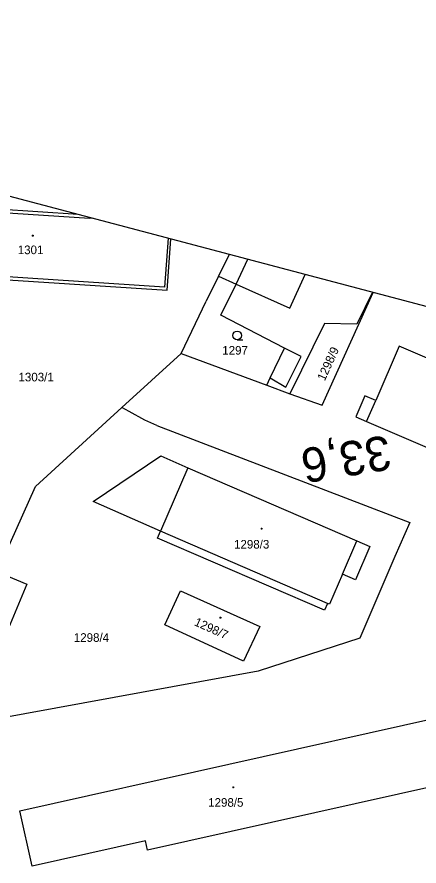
# Model space of a CAD drawing. Extents: x -805011 to -803920, y -1150790 to -1150234.
# Drawn here: x -804499.4 to -804429.5, y -1150466 to -1150318.2 of the extents above; entities that cross this region are included whole.
import ezdxf

# ---------------------------------------------------------------- set-up
doc = ezdxf.new("R2010")
doc.units = 0
for name, color, linetype in [('Default', 7, 'Continuous'), ('formát', 7, 'Continuous'), ('kilometráž - vrstava 7', 7, 'Continuous'), ('kn_celek - Cisla pozemkovych parcel', 7, 'Continuous'), ('kn_celek - Cisla stavebnich parcel', 7, 'Continuous'), ('kn_celek - Hranice parcel', 7, 'Continuous'), ('kn_celek - Vnitrni kresby', 7, 'Continuous'), ('kn_celek - Znacky budov', 7, 'Continuous'), ('kn_celek - Znacky kultur', 7, 'Continuous')]:
    doc.layers.add(name, color=color, linetype=linetype)

# ---------------------------------------------------------------- blocks, each defined once
blk = doc.blocks.new('304')
at = {"layer": 'Default'}
blk.add_line((-0.1, 0), (9.9, 0), dxfattribs=at)
blk.add_circle((-0.1, 7.5), 7.5, dxfattribs=at)
blk = doc.blocks.new('402')
at = {"layer": 'Default'}
for p, q in [((-0.8, 0.8), (0.7, 0.8)), ((-0.8, 0.8), (-0.8, -0.7)), ((0.7, 0.8), (0.7, -0.7)), ((0.7, -0.7), (-0.8, -0.7))]:
    blk.add_line(p, q, dxfattribs=at)

msp = doc.modelspace()

# ---------------------------------------------------------------- linework, layer by layer
at = {"layer": 'formát'}
msp.add_line((-804326.3, -1150395.58), (-804935.34, -1150234.42), dxfattribs=at)
at = {"layer": 'kn_celek - Hranice parcel'}
for p, q in [((-804488.71, -1150352.61), (-804503.36, -1150351.63)), ((-804473.23, -1150365.78), (-804472.61, -1150356.87)), ((-804464.31, -1150363.35), (-804462.43, -1150359.56)), ((-804519.49, -1150362.73), (-804473.23, -1150365.78)), ((-804464.31, -1150363.35), (-804466.46, -1150367.67)), ((-804464.31, -1150363.35), (-804461.25, -1150364.73)), ((-804463.92, -1150370.13), (-804461.25, -1150364.73)), ((-804446.28, -1150385.78), (-804437.43, -1150366.18)), ((-804437.55, -1150366.14), (-804440.24, -1150371.68)), ((-804470.79, -1150376.79), (-804466.46, -1150367.67)), ((-804452.82, -1150375.84), (-804463.92, -1150370.13)), ((-804445.89, -1150371.55), (-804451.93, -1150383.79)), ((-804440.24, -1150371.68), (-804445.89, -1150371.55)), ((-804455.33, -1150381.05), (-804452.82, -1150375.84)), ((-804432.88, -1150375.5), (-804436.98, -1150384.97)), ((-804404.52, -1150387.76), (-804432.88, -1150375.5)), ((-804470.79, -1150376.79), (-804481.13, -1150386.22)), ((-804470.79, -1150376.79), (-804455.94, -1150382.3)), ((-804455.94, -1150382.3), (-804455.33, -1150381.05)), ((-804455.94, -1150382.3), (-804451.93, -1150383.79)), ((-804451.93, -1150383.79), (-804446.28, -1150385.78)), ((-804438.88, -1150384.15), (-804440.46, -1150387.81)), ((-804436.98, -1150384.97), (-804438.88, -1150384.15)), ((-804496.15, -1150399.93), (-804481.13, -1150386.22)), ((-804479.87, -1150386.91), (-804481.13, -1150386.22)), ((-804477.15, -1150388.39), (-804479.87, -1150386.91)), ((-804475.07, -1150389.32), (-804477.15, -1150388.39)), ((-804440.46, -1150387.81), (-804438.58, -1150388.63)), ((-804438.58, -1150388.63), (-804410.14, -1150400.87)), ((-804475.07, -1150389.32), (-804431.06, -1150406.23)), ((-804486.1, -1150402.56), (-804474.37, -1150394.64)), ((-804474.37, -1150394.64), (-804469.64, -1150396.73)), ((-804469.64, -1150396.73), (-804440.25, -1150409.44)), ((-804507.58, -1150425.47), (-804496.15, -1150399.93)), ((-804474.41, -1150407.75), (-804486.1, -1150402.56)), ((-804431.06, -1150406.23), (-804433.64, -1150412.12)), ((-804474.93, -1150408.95), (-804474.41, -1150407.75)), ((-804445.88, -1150421.51), (-804474.93, -1150408.95)), ((-804440.25, -1150409.44), (-804438.01, -1150410.41)), ((-804438.01, -1150410.41), (-804440.51, -1150416.19)), ((-804433.64, -1150412.12), (-804439.74, -1150426.35)), ((-804501.23, -1150415.44), (-804497.65, -1150416.93)), ((-804442.75, -1150415.22), (-804445.02, -1150420.46)), ((-804440.51, -1150416.19), (-804442.75, -1150415.22)), ((-804497.65, -1150416.93), (-804501.68, -1150426.69)), ((-804473.68, -1150424.06), (-804470.93, -1150418.09)), ((-804470.93, -1150418.09), (-804457.13, -1150424.3)), ((-804445.36, -1150420.31), (-804445.88, -1150421.51)), ((-804445.02, -1150420.46), (-804445.36, -1150420.31)), ((-804459.96, -1150430.39), (-804473.68, -1150424.06)), ((-804457.13, -1150424.3), (-804459.96, -1150430.39)), ((-804439.74, -1150426.35), (-804457.42, -1150432.08)), ((-804457.42, -1150432.08), (-804541.27, -1150447.49)), ((-804498.86, -1150456.4), (-804426.19, -1150440.19)), ((-804425.85, -1150451.92), (-804476.67, -1150463.25)), ((-804496.72, -1150466.03), (-804498.86, -1150456.4)), ((-804477.02, -1150461.66), (-804496.72, -1150466.03)), ((-804476.67, -1150463.25), (-804477.02, -1150461.66))]:
    msp.add_line(p, q, dxfattribs=at)
at = {"layer": 'kn_celek - Vnitrni kresby'}
for p, q in [((-804503.37, -1150352.16), (-804486.73, -1150353.26)), ((-804486.72, -1150353.13), (-804486.73, -1150353.26)), ((-804486.07, -1150353.31), (-804486.73, -1150353.26)), ((-804473.09, -1150356.74), (-804473.7, -1150365.24)), ((-804461.25, -1150364.73), (-804459.25, -1150360.4)), ((-804473.7, -1150365.24), (-804517.87, -1150362.32)), ((-804451.93, -1150368.93), (-804449.27, -1150363.04)), ((-804461.25, -1150364.73), (-804451.93, -1150368.93)), ((-804449.97, -1150377.31), (-804452.82, -1150375.84)), ((-804452.6, -1150382.65), (-804449.97, -1150377.31)), ((-804455.33, -1150381.05), (-804452.6, -1150382.65)), ((-804438.58, -1150388.63), (-804436.98, -1150384.97)), ((-804469.64, -1150396.73), (-804474.41, -1150407.75)), ((-804445.36, -1150420.31), (-804474.41, -1150407.75)), ((-804442.75, -1150415.22), (-804440.25, -1150409.44))]:
    msp.add_line(p, q, dxfattribs=at)

# ---------------------------------------------------------------- block references
at = {"layer": 'kn_celek - Znacky budov', "xscale": 0.1, "yscale": 0.10000000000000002}
for p in [(-804496.64, -1150356.27), (-804456.85, -1150407.31), (-804463.99, -1150422.79), (-804461.77, -1150452.32)]:
    msp.add_blockref('402', p, dxfattribs=at)
at = {"layer": 'kn_celek - Znacky kultur', "xscale": 0.1, "yscale": 0.10000000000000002}
msp.add_blockref('304', (-804461.07, -1150374.39), dxfattribs=at)

# ---------------------------------------------------------------- texts
at = {"layer": 'kilometráž - vrstava 7'}
msp.add_text('33,6', height=6, rotation=189.2666, dxfattribs=at).set_placement((-804434.88, -1150390.97))
at = {"layer": 'kn_celek - Cisla pozemkovych parcel'}
for s, p in [('1297', (-804463.67, -1150376.99)), ('1303/1', (-804499.1, -1150381.65)), ('1298/4', (-804489.48, -1150427))]:
    msp.add_text(s, height=1.5, dxfattribs=at).set_placement(p)
msp.add_text('1298/9', height=1.5, rotation=65.7, dxfattribs=at).set_placement((-804445.85, -1150381.68))
at = {"layer": 'kn_celek - Cisla stavebnich parcel'}
for s, p in [('1301', (-804499.23, -1150359.5)), ('1298/3', (-804461.62, -1150410.76)), ('1298/5', (-804466.12, -1150455.71))]:
    msp.add_text(s, height=1.5, dxfattribs=at).set_placement(p)
msp.add_text('1298/7', height=1.5, rotation=335.7, dxfattribs=at).set_placement((-804468.66, -1150424.07))

doc.saveas('drawing.dxf')
